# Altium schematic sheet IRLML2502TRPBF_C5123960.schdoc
size 127 x 101 mm
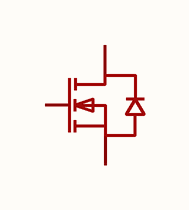
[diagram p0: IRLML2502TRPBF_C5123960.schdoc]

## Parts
Q?  irlml2502trpbf_c5123960  [SOT-23_L2.9-W1.3-P1.90-LS2.4-BR]  (value not drawn)

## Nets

Not connected (* = marked no-connect by the designer): Q? 1(G) 2(S) 3(D)

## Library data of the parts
Q? = irlml2502trpbf_c5123960: 漏源电压(Vdss):20V;连续漏极电流(Id):6A;导通电阻(RDS(on)):35mΩ@4.5V,6A;耗散功率(Pd):1.25W;阈值电压(Vgs(th)):1V;; Manufacturer: TECH PUBLIC(台舟); AddInBom: yes; ModelId: c62791f0466c4ae2a892c056b845b0ca; ModelName: SOT-23-3P_L2.9-W1.3-H1.0-LS2.4-P0.95; ModelTransform: 98.64468,114.173,0,180,0,0,0.001,-0.002,0; Drain to Source Voltage: 20V; Pd - Power Dissipation: 1.25W; Gate Threshold Voltage (Vgs(th)): 1V; Gate Charge(Qg): 7.7nC@4.5V; Input Capacitance(Ciss): 574pF@10V; Reverse Transfer Capacitance (Crss@Vds): 60pF; Output Capacitance(Coss): 70pF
